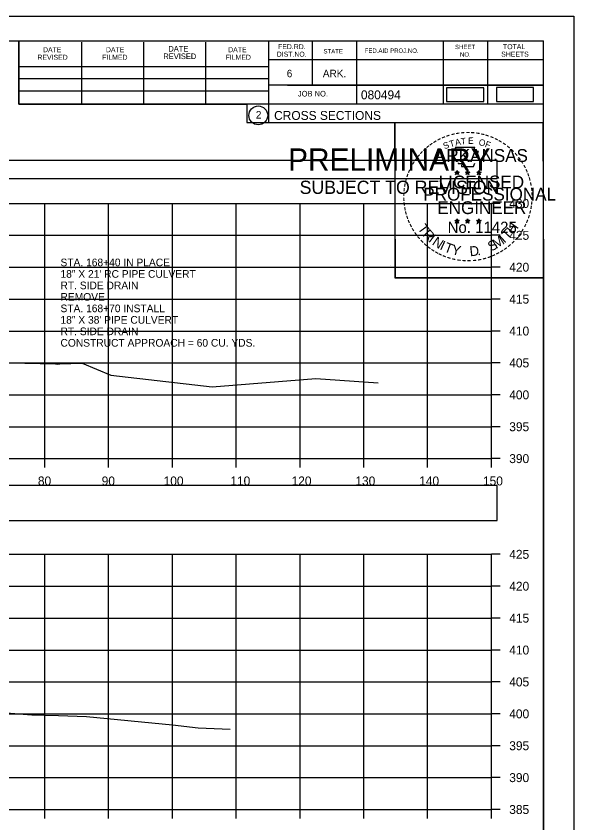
# Model space of a CAD drawing. Extents: x 1376273 to 1384221, y 378927 to 384592.
# Drawn here: x 1377933.8 to 1378021.2, y 381052.1 to 381178.5 of the extents above; entities that cross this region are included whole.
import ezdxf

# ---------------------------------------------------------------- set-up
doc = ezdxf.new("R2010")
doc.units = 0
for name, color, linetype in [('R_Axis', 7, 'Continuous'), ('R_Axis Annot', 7, 'Continuous'), ('R_Border', 7, 'Continuous'), ('R_Border PE', 7, 'Continuous'), ('R_Border Prem', 7, 'Continuous'), ('R_Drive', 7, 'Continuous'), ('R_Exist Surface', 7, 'Continuous'), ('R_Grid', 7, 'Continuous'), ('R_No Plot', 7, 'Continuous')]:
    doc.layers.add(name, color=color, linetype=linetype)

msp = doc.modelspace()

# ---------------------------------------------------------------- linework, layer by layer
at = {"layer": 'R_Axis'}
for p, q in [((1378008.28, 381109.17), (1378008.28, 381149.17)), ((1378009.68, 381149.17), (1378008.28, 381149.17)), ((1378009.68, 381144.17), (1378008.28, 381144.17)), ((1378009.68, 381139.17), (1378008.28, 381139.17)), ((1378009.68, 381134.17), (1378008.28, 381134.17)), ((1378009.68, 381129.17), (1378008.28, 381129.17)), ((1378009.68, 381124.17), (1378008.28, 381124.17)), ((1378009.68, 381119.17), (1378008.28, 381119.17)), ((1378009.68, 381114.17), (1378008.28, 381114.17)), ((1377708.28, 381109.17), (1378008.28, 381109.17)), ((1377938.28, 381107.77), (1377938.28, 381109.17)), ((1377948.28, 381107.77), (1377948.28, 381109.17)), ((1377958.28, 381107.77), (1377958.28, 381109.17)), ((1377968.28, 381107.77), (1377968.28, 381109.17)), ((1377978.28, 381107.77), (1377978.28, 381109.17)), ((1377988.28, 381107.77), (1377988.28, 381109.17)), ((1377998.28, 381107.77), (1377998.28, 381109.17)), ((1378008.28, 381107.77), (1378008.28, 381109.17)), ((1378009.68, 381109.17), (1378008.28, 381109.17)), ((1378008.28, 381054.17), (1378008.28, 381094.17)), ((1378009.68, 381094.17), (1378008.28, 381094.17)), ((1378009.68, 381089.17), (1378008.28, 381089.17)), ((1378009.68, 381084.17), (1378008.28, 381084.17)), ((1378009.68, 381079.17), (1378008.28, 381079.17)), ((1378009.68, 381074.17), (1378008.28, 381074.17)), ((1378009.68, 381069.17), (1378008.28, 381069.17)), ((1378009.68, 381064.17), (1378008.28, 381064.17)), ((1378009.68, 381059.17), (1378008.28, 381059.17)), ((1377708.28, 381054.17), (1378008.28, 381054.17)), ((1377938.28, 381052.77), (1377938.28, 381054.17)), ((1377948.28, 381052.77), (1377948.28, 381054.17)), ((1377958.28, 381052.77), (1377958.28, 381054.17)), ((1377968.28, 381052.77), (1377968.28, 381054.17)), ((1377978.28, 381052.77), (1377978.28, 381054.17)), ((1377988.28, 381052.77), (1377988.28, 381054.17)), ((1377998.28, 381052.77), (1377998.28, 381054.17)), ((1378008.28, 381052.77), (1378008.28, 381054.17)), ((1378009.68, 381054.17), (1378008.28, 381054.17))]:
    msp.add_line(p, q, dxfattribs=at)
at = {"layer": 'R_Axis Annot'}
for points in [[(1377707.37, 381153.1), (1378009.17, 381153.1), (1378009.17, 381155.92), (1377707.37, 381155.92)], [(1377707.37, 381099.45), (1378009.17, 381099.45), (1378009.17, 381104.97), (1377707.37, 381104.97)]]:
    msp.add_lwpolyline(points, close=True, dxfattribs=at)
at = {"layer": 'R_Border'}
for p, q in [((1377700.28, 381174.63), (1378016.46, 381174.63)), ((1377934.2, 381164.75), (1377934.2, 381174.63)), ((1377944.06, 381164.75), (1377944.06, 381174.43)), ((1377953.82, 381164.75), (1377953.82, 381174.43)), ((1377963.5, 381164.75), (1377963.5, 381174.43)), ((1377973.36, 381174.63), (1377973.36, 381161.83)), ((1377980.2, 381174.63), (1377980.2, 381167.69)), ((1377987.14, 381174.63), (1377987.14, 381164.75)), ((1378000.72, 381174.63), (1378000.72, 381164.75)), ((1378007.66, 381174.63), (1378007.66, 381164.75)), ((1378016.46, 380969.17), (1378016.46, 381174.63)), ((1378016.46, 381171.69), (1377973.36, 381171.69)), ((1378016.46, 381171.71), (1378016.46, 381171.71)), ((1377934.2, 381170.61), (1377973.36, 381170.61)), ((1377934.2, 381168.75), (1377973.36, 381168.75)), ((1378016.46, 381167.69), (1377973.36, 381167.69)), ((1377976.32, 381167.69), (1378016.46, 381167.69)), ((1377934.2, 381164.75), (1377934.2, 381166.81)), ((1377934.2, 381166.81), (1377973.36, 381166.81)), ((1378016.46, 381164.75), (1377934.2, 381164.75)), ((1377973.36, 381161.83), (1378016.46, 381161.83))]:
    msp.add_line(p, q, dxfattribs=at)
msp.add_circle((1377971.74, 381162.97), 1.47, dxfattribs=at)
at = {"layer": 'R_Border PE'}
for p, q in [((1378002.54, 381154.09), (1378002.89, 381153.97)), ((1378002.54, 381154.09), (1378002.8, 381154.04)), ((1378002.54, 381154.09), (1378002.78, 381153.96)), ((1378002.68, 381153.68), (1378002.89, 381153.97)), ((1378002.68, 381153.68), (1378002.8, 381153.92)), ((1378002.68, 381153.68), (1378002.89, 381153.89)), ((1378002.89, 381154.34), (1378002.85, 381154.09)), ((1378002.89, 381153.97), (1378002.89, 381154.34)), ((1378002.89, 381154.34), (1378002.94, 381154.09)), ((1378003.24, 381154.09), (1378002.89, 381153.97)), ((1378003.1, 381153.68), (1378002.89, 381153.97)), ((1378003.1, 381153.68), (1378002.89, 381153.89)), ((1378003.24, 381154.09), (1378002.95, 381154.04)), ((1378003.1, 381153.68), (1378002.97, 381153.97)), ((1378003.24, 381154.09), (1378003.03, 381153.98)), ((1378004.21, 381154.09), (1378004.56, 381153.97)), ((1378004.21, 381154.09), (1378004.47, 381154.04)), ((1378004.21, 381154.09), (1378004.45, 381153.96)), ((1378004.35, 381153.68), (1378004.56, 381153.97)), ((1378004.35, 381153.68), (1378004.47, 381153.92)), ((1378004.35, 381153.68), (1378004.56, 381153.89)), ((1378004.56, 381154.34), (1378004.52, 381154.09)), ((1378004.56, 381153.97), (1378004.56, 381154.34)), ((1378004.56, 381154.34), (1378004.61, 381154.09)), ((1378004.91, 381154.09), (1378004.56, 381153.97)), ((1378004.77, 381153.68), (1378004.56, 381153.97)), ((1378004.77, 381153.68), (1378004.56, 381153.89)), ((1378004.91, 381154.09), (1378004.62, 381154.04)), ((1378004.77, 381153.68), (1378004.64, 381153.97)), ((1378004.91, 381154.09), (1378004.7, 381153.98)), ((1378005.98, 381154.07), (1378006.33, 381153.96)), ((1378005.98, 381154.07), (1378006.23, 381154.03)), ((1378005.98, 381154.07), (1378006.21, 381153.95)), ((1378006.11, 381153.67), (1378006.33, 381153.96)), ((1378006.11, 381153.67), (1378006.24, 381153.91)), ((1378006.11, 381153.67), (1378006.32, 381153.88)), ((1378006.33, 381154.33), (1378006.28, 381154.08)), ((1378006.54, 381153.67), (1378006.32, 381153.88)), ((1378006.33, 381153.96), (1378006.33, 381154.33)), ((1378006.33, 381154.33), (1378006.37, 381154.08)), ((1378006.67, 381154.07), (1378006.33, 381153.96)), ((1378006.54, 381153.67), (1378006.33, 381153.96)), ((1378006.67, 381154.07), (1378006.39, 381154.02)), ((1378006.54, 381153.67), (1378006.4, 381153.96)), ((1378006.67, 381154.07), (1378006.47, 381153.97)), ((1378002.54, 381146.51), (1378002.89, 381146.4)), ((1378002.54, 381146.51), (1378002.79, 381146.47)), ((1378002.54, 381146.51), (1378002.78, 381146.39)), ((1378002.67, 381146.1), (1378002.89, 381146.4)), ((1378002.67, 381146.1), (1378002.8, 381146.35)), ((1378002.67, 381146.1), (1378002.89, 381146.32)), ((1378002.89, 381146.77), (1378002.85, 381146.51)), ((1378002.89, 381146.4), (1378002.89, 381146.77)), ((1378002.89, 381146.77), (1378002.94, 381146.52)), ((1378003.23, 381146.51), (1378002.89, 381146.4)), ((1378003.1, 381146.1), (1378002.89, 381146.4)), ((1378003.1, 381146.1), (1378002.89, 381146.32)), ((1378003.23, 381146.51), (1378002.95, 381146.46)), ((1378003.1, 381146.1), (1378002.96, 381146.4)), ((1378003.23, 381146.51), (1378003.03, 381146.41)), ((1378004.21, 381146.51), (1378004.56, 381146.4)), ((1378004.21, 381146.51), (1378004.46, 381146.47)), ((1378004.21, 381146.51), (1378004.44, 381146.39)), ((1378004.34, 381146.1), (1378004.56, 381146.4)), ((1378004.34, 381146.1), (1378004.47, 381146.35)), ((1378004.34, 381146.1), (1378004.55, 381146.32)), ((1378004.56, 381146.77), (1378004.52, 381146.51)), ((1378004.77, 381146.1), (1378004.55, 381146.32)), ((1378004.56, 381146.4), (1378004.56, 381146.77)), ((1378004.56, 381146.77), (1378004.61, 381146.52)), ((1378004.9, 381146.51), (1378004.56, 381146.4)), ((1378004.77, 381146.1), (1378004.56, 381146.4)), ((1378004.9, 381146.51), (1378004.62, 381146.46)), ((1378004.77, 381146.1), (1378004.63, 381146.4)), ((1378004.9, 381146.51), (1378004.7, 381146.41)), ((1378005.97, 381146.5), (1378006.32, 381146.39)), ((1378005.97, 381146.5), (1378006.23, 381146.46)), ((1378005.97, 381146.5), (1378006.21, 381146.38)), ((1378006.11, 381146.09), (1378006.32, 381146.39)), ((1378006.11, 381146.09), (1378006.23, 381146.34)), ((1378006.11, 381146.09), (1378006.32, 381146.31)), ((1378006.32, 381146.76), (1378006.28, 381146.5)), ((1378006.32, 381146.39), (1378006.32, 381146.76)), ((1378006.32, 381146.76), (1378006.37, 381146.51)), ((1378006.67, 381146.5), (1378006.32, 381146.39)), ((1378006.54, 381146.09), (1378006.32, 381146.39)), ((1378006.54, 381146.09), (1378006.32, 381146.31)), ((1378006.67, 381146.5), (1378006.38, 381146.45)), ((1378006.54, 381146.09), (1378006.4, 381146.39)), ((1378006.67, 381146.5), (1378006.47, 381146.4))]:
    msp.add_line(p, q, dxfattribs=at)
for points in [[(1378002.58, 381157.96), (1378002.85, 381157.14)], [(1378006.09, 381157.04), (1378006.24, 381157.33), (1378005.55, 381157.3), (1378005.7, 381157.96), (1378002.58, 381157.96)], [(1378003.08, 381155.54), (1378003.08, 381155.45), (1378003.64, 381155.43), (1378003.58, 381154.96), (1378005.45, 381154.96), (1378005.66, 381155.5)], [(1378002.89, 381154.34), (1378003.1, 381153.68), (1378002.54, 381154.09), (1378003.24, 381154.09), (1378002.68, 381153.68), (1378002.89, 381154.34)], [(1378004.56, 381154.34), (1378004.77, 381153.68), (1378004.21, 381154.09), (1378004.91, 381154.09), (1378004.35, 381153.68), (1378004.56, 381154.34)], [(1378006.33, 381154.33), (1378006.54, 381153.67), (1378005.98, 381154.07), (1378006.67, 381154.07), (1378006.11, 381153.67), (1378006.33, 381154.33)], [(1378002.89, 381146.77), (1378003.1, 381146.1), (1378002.54, 381146.51), (1378003.23, 381146.51), (1378002.67, 381146.1), (1378002.89, 381146.77)], [(1378004.56, 381146.77), (1378004.77, 381146.1), (1378004.21, 381146.51), (1378004.9, 381146.51), (1378004.34, 381146.1), (1378004.56, 381146.77)], [(1378006.32, 381146.76), (1378006.54, 381146.09), (1378005.97, 381146.5), (1378006.67, 381146.5), (1378006.11, 381146.09), (1378006.32, 381146.76)]]:
    msp.add_lwpolyline(points, dxfattribs=at)
for centre, radius in [((1378002.89, 381153.97), 0.172), ((1378002.89, 381153.97), 0.145), ((1378002.89, 381153.97), 0.116), ((1378002.89, 381153.97), 0.0991), ((1378002.89, 381153.97), 0.0747), ((1378002.89, 381153.97), 0.0495), ((1378002.89, 381153.97), 0.0296), ((1378004.56, 381153.97), 0.172), ((1378004.56, 381153.97), 0.145), ((1378004.56, 381153.97), 0.116), ((1378004.56, 381153.97), 0.0991), ((1378004.56, 381153.97), 0.0747), ((1378004.56, 381153.97), 0.0495), ((1378004.56, 381153.97), 0.0296), ((1378006.32, 381153.96), 0.172), ((1378006.32, 381153.96), 0.145), ((1378006.32, 381153.96), 0.116), ((1378006.32, 381153.96), 0.0991), ((1378006.32, 381153.96), 0.0747), ((1378006.32, 381153.96), 0.0495), ((1378006.32, 381153.96), 0.0296), ((1378002.89, 381146.4), 0.172), ((1378002.89, 381146.4), 0.145), ((1378002.89, 381146.4), 0.116), ((1378002.89, 381146.4), 0.0991), ((1378002.89, 381146.4), 0.0747), ((1378002.89, 381146.4), 0.0495), ((1378002.89, 381146.4), 0.0296), ((1378004.56, 381146.4), 0.172), ((1378004.56, 381146.4), 0.145), ((1378004.56, 381146.4), 0.116), ((1378004.56, 381146.4), 0.0991), ((1378004.56, 381146.4), 0.0747), ((1378004.56, 381146.4), 0.0495), ((1378004.56, 381146.4), 0.0296), ((1378006.32, 381146.39), 0.172), ((1378006.32, 381146.39), 0.145), ((1378006.32, 381146.39), 0.116), ((1378006.32, 381146.39), 0.0991), ((1378006.32, 381146.39), 0.0747), ((1378006.32, 381146.39), 0.0495), ((1378006.32, 381146.39), 0.0296)]:
    msp.add_circle(centre, radius, dxfattribs=at)
at = {"layer": 'R_Drive'}
for points in [[(1378001.25, 381165.13), (1378007.09, 381165.13), (1378007.09, 381167.31), (1378001.25, 381167.31)], [(1378009.06, 381165.13), (1378014.9, 381165.13), (1378014.9, 381167.32), (1378009.06, 381167.32)]]:
    msp.add_lwpolyline(points, close=True, dxfattribs=at)
at = {"layer": 'R_Exist Surface'}
for points in [[(1377927.43, 381124.32), (1377935.15, 381124.13), (1377939.95, 381124.01), (1377940.26, 381123.99), (1377940.61, 381124.01), (1377944.11, 381124.11), (1377948.65, 381122.25), (1377964.53, 381120.42), (1377980.75, 381121.74), (1377990.55, 381121.05)], [(1377927.44, 381069.67), (1377936.25, 381069.02), (1377940.44, 381068.92), (1377944.8, 381068.75), (1377958.29, 381067.44), (1377962.34, 381066.98), (1377967.32, 381066.77)]]:
    msp.add_lwpolyline(points, dxfattribs=at)
at = {"layer": 'R_Grid'}
for p, q in [((1377708.28, 381149.17), (1378008.28, 381149.17)), ((1377938.28, 381109.17), (1377938.28, 381149.17)), ((1377948.28, 381109.17), (1377948.28, 381149.17)), ((1377958.28, 381109.17), (1377958.28, 381149.17)), ((1377968.28, 381109.17), (1377968.28, 381149.17)), ((1377978.28, 381109.17), (1377978.28, 381149.17)), ((1377988.28, 381109.17), (1377988.28, 381149.17)), ((1377998.28, 381109.17), (1377998.28, 381149.17)), ((1378008.28, 381109.17), (1378008.28, 381149.17)), ((1377708.28, 381144.17), (1378008.28, 381144.17)), ((1377708.28, 381139.17), (1378008.28, 381139.17)), ((1377708.28, 381134.17), (1378008.28, 381134.17)), ((1377708.28, 381129.17), (1378008.28, 381129.17)), ((1377708.28, 381124.17), (1378008.28, 381124.17)), ((1377708.28, 381119.17), (1378008.28, 381119.17)), ((1377708.28, 381114.17), (1378008.28, 381114.17)), ((1377708.28, 381109.17), (1378008.28, 381109.17)), ((1377708.28, 381094.17), (1378008.28, 381094.17)), ((1377938.28, 381054.17), (1377938.28, 381094.17)), ((1377948.28, 381054.17), (1377948.28, 381094.17)), ((1377958.28, 381054.17), (1377958.28, 381094.17)), ((1377968.28, 381054.17), (1377968.28, 381094.17)), ((1377978.28, 381054.17), (1377978.28, 381094.17)), ((1377988.28, 381054.17), (1377988.28, 381094.17)), ((1377998.28, 381054.17), (1377998.28, 381094.17)), ((1378008.28, 381054.17), (1378008.28, 381094.17)), ((1377708.28, 381089.17), (1378008.28, 381089.17)), ((1377708.28, 381084.17), (1378008.28, 381084.17)), ((1377708.28, 381079.17), (1378008.28, 381079.17)), ((1377708.28, 381074.17), (1378008.28, 381074.17)), ((1377708.28, 381069.17), (1378008.28, 381069.17)), ((1377708.28, 381064.17), (1378008.28, 381064.17)), ((1377708.28, 381059.17), (1378008.28, 381059.17)), ((1377708.28, 381054.17), (1378008.28, 381054.17))]:
    msp.add_line(p, q, dxfattribs=at)
at = {"layer": 'R_No Plot'}
for p, q in [((1377687.88, 381178.52), (1378021.21, 381178.52)), ((1377992.49, 381139.37), (1377992.49, 381139.37))]:
    msp.add_line(p, q, dxfattribs=at)
for points in [[(1377687.87, 381178.52), (1378021.21, 381178.52), (1378021.21, 380965.19), (1377687.87, 380965.19)], [(1377934.2, 381174.63), (1377934.2, 381164.75), (1377969.93, 381164.75), (1377969.93, 381161.83), (1377993.13, 381161.83), (1377993.13, 381137.5), (1378016.46, 381137.5), (1378016.46, 380969.17), (1377700.28, 380969.17), (1377700.28, 381174.63)], [(1377993.13, 381161.83), (1378016.34, 381161.83), (1378016.46, 381137.5), (1377993.25, 381137.5)]]:
    msp.add_lwpolyline(points, close=True, dxfattribs=at)

# ---------------------------------------------------------------- texts
at = {"layer": 'R_Axis Annot'}
for s, height, p in [('430', 1.4, (1378011.08, 381148.47)), ('425', 1.4, (1378011.08, 381143.47)), ('STA. 168+40 IN PLACE', 1.2, (1377940.73, 381139.32)), ('420', 1.4, (1378011.08, 381138.47)), ('18" X 21\' RC PIPE CULVERT', 1.2, (1377940.73, 381137.52)), ('RT. SIDE DRAIN', 1.2, (1377940.73, 381135.72)), ('REMOVE ', 1.2, (1377940.73, 381133.92)), ('415', 1.4, (1378011.08, 381133.47)), ('STA. 168+70 INSTALL', 1.2, (1377940.73, 381132.12)), ('18" X 38\' PIPE CULVERT', 1.2, (1377940.73, 381130.32)), ('RT. SIDE DRAIN', 1.2, (1377940.73, 381128.52)), ('410', 1.4, (1378011.08, 381128.47)), ('CONSTRUCT APPROACH = 60 CU. YDS.', 1.2, (1377940.73, 381126.72)), ('405', 1.4, (1378011.08, 381123.47)), ('400', 1.4, (1378011.08, 381118.47)), ('395', 1.4, (1378011.08, 381113.47)), ('390', 1.4, (1378011.08, 381108.47)), ('80', 1.4, (1377937.19, 381104.97)), ('90', 1.4, (1377947.19, 381104.97)), ('100', 1.4, (1377956.9, 381104.97)), ('110', 1.4, (1377967.36, 381104.97)), ('120', 1.4, (1377976.96, 381104.97)), ('130', 1.4, (1377986.96, 381104.97)), ('140', 1.4, (1377996.96, 381104.97)), ('150', 1.4, (1378006.96, 381104.97)), ('425', 1.4, (1378011.08, 381093.47)), ('420', 1.4, (1378011.08, 381088.47)), ('415', 1.4, (1378011.08, 381083.47)), ('410', 1.4, (1378011.08, 381078.47)), ('405', 1.4, (1378011.08, 381073.47)), ('400', 1.4, (1378011.08, 381068.47)), ('395', 1.4, (1378011.08, 381063.47)), ('390', 1.4, (1378011.08, 381058.47)), ('385', 1.4, (1378011.08, 381053.47))]:
    msp.add_text(s, height=height, dxfattribs=at).set_placement(p)
at = {"layer": 'R_Border'}
for s, height, p in [('DATE', 0.879, (1377957.64, 381172.97)), ('FED.RD.', 0.782, (1377974.84, 381173.35)), ('SHEET', 0.684, (1378002.58, 381173.35)), ('TOTAL', 0.782, (1378010.1, 381173.35)), ('REVISED', 0.782, (1377937.12, 381171.69)), ('DATE', 0.782, (1377938, 381172.87)), ('FILMED', 0.782, (1377947.28, 381171.69)), ('DATE', 0.782, (1377947.86, 381172.87)), ('REVISED', 0.879, (1377956.86, 381171.79)), ('FILMED', 0.782, (1377966.62, 381171.69)), ('DATE', 0.782, (1377967.02, 381172.87)), ('DIST.NO.', 0.782, (1377974.64, 381172.17)), ('STATE', 0.684, (1377981.96, 381172.67)), ('FED.AID PROJ.NO.', 0.684, (1377988.42, 381172.77)), ('NO.', 0.684, (1378003.36, 381172.17)), ('SHEETS', 0.782, (1378009.82, 381172.17)), ('6', 1.17, (1377976.2, 381168.95)), ('ARK.', 1.172, (1377981.86, 381168.95)), ('JOB NO.', 0.879, (1377977.96, 381165.93)), ('080494', 1.4, (1377987.83, 381165.49)), ('2', 1.17, (1377971.36, 381162.48)), ('CROSS SECTIONS', 1.4, (1377974.22, 381162.26))]:
    msp.add_text(s, height=height, rotation=360, dxfattribs=at).set_placement(p)
at = {"layer": 'R_Border PE'}
for s, height, rotation, p in [('-', 1.6, 19.1761, (1378001.33, 381159.09)), ('-', 1.6, 13.6301, (1378002.08, 381159.33)), ('-', 1.6, 10.2193, (1378002.76, 381159.49)), ('-', 1.6, 5.8968, (1378003.49, 381159.6)), ('-', 1.6, 0.1862, (1378004.26, 381159.68)), ('-', 1.6, 357.743, (1378004.98, 381159.66)), ('-', 1.6, 352.1617, (1378005.73, 381159.61)), ('-', 1.6, 347.2049, (1378006.45, 381159.49)), ('-', 1.6, 342.3362, (1378007.08, 381159.34)), ('-', 1.6, 36.2317, (1377998.89, 381157.74)), ('-', 1.6, 34.0636, (1377999.47, 381158.13)), ('-', 1.6, 28.7918, (1378000.06, 381158.5)), ('-', 1.6, 24.3072, (1378000.7, 381158.82)), ('S', 1, 21.594, (1378000.94, 381157.64)), ('T', 1, 16.4036, (1378001.85, 381157.97)), ('A', 1, 11.2132, (1378002.68, 381158.22)), ('T', 1, 6.0228, (1378003.53, 381158.39)), ('E', 1, 0.8323, (1378004.63, 381158.5)), ('O', 1, 350.4515, (1378006.24, 381158.29)), ('F', 1, 340.0707, (1378007.19, 381158.06)), ('-', 1.6, 337.8551, (1378007.82, 381159.11)), ('-', 1.6, 334.1211, (1378008.45, 381158.84)), ('-', 1.6, 329.6409, (1378009.03, 381158.56)), ('-', 1.6, 325.8627, (1378009.67, 381158.2)), ('-', 1.6, 48.423, (1377997.53, 381156.47)), ('-', 1.6, 42.9622, (1377997.98, 381156.94)), ('-', 1.6, 38.9507, (1377998.41, 381157.36)), ('ARKANSAS', 2, 360, (1377999.44, 381155.68)), ('-', 1.6, 320.5297, (1378010.28, 381157.77)), ('-', 1.6, 315.5786, (1378010.88, 381157.29)), ('-', 1.6, 54.2325, (1377996.72, 381155.41)), ('-', 1.6, 50.6142, (1377997.13, 381155.98)), ('-', 1.6, 309.8797, (1378011.45, 381156.74)), ('-', 1.6, 306.6522, (1378011.97, 381156.13)), ('-', 1.6, 62.8713, (1377996.08, 381154.27)), ('-', 1.6, 58.0706, (1377996.39, 381154.89)), ('-', 1.4, 303.6753, (1378012.46, 381155.57)), ('-', 1.6, 299.6684, (1378012.78, 381154.96)), ('-', 1.6, 72.3945, (1377995.6, 381153.03)), ('-', 1.6, 67.7743, (1377995.82, 381153.66)), ('LICENSED', 2, 360, (1378000.03, 381151.53)), ('DWB', 0.01, 360, (1378002.88, 381153.97)), ('DWB', 0.01, 360, (1378004.55, 381153.97)), ('DWB', 0.01, 360, (1378006.31, 381153.96)), ('-', 1.6, 294.6628, (1378013.1, 381154.35)), ('-', 1.6, 290.5728, (1378013.36, 381153.77)), ('-', 1.6, 81.2013, (1377995.27, 381151.6)), ('-', 1.6, 75.461, (1377995.4, 381152.32)), ('-', 1.6, 285.1233, (1378013.59, 381153.19)), ('-', 1.6, 280.5493, (1378013.79, 381152.45)), ('-', 1.6, 85.1863, (1377995.19, 381150.91)), ('PROFESSIONAL', 2, 360, (1377997.61, 381149.62)), ('-', 1.6, 276.5962, (1378013.95, 381151.68)), ('-', 1.6, 94.1959, (1377995.2, 381149.49)), ('-', 1.6, 89.0622, (1377995.17, 381150.21)), ('-', 1.6, 274.3301, (1378014.01, 381150.96)), ('-', 1.6, 269.9407, (1378014.05, 381150.33)), ('-', 1.6, 98.9479, (1377995.28, 381148.82)), ('-', 1.6, 101.7149, (1377995.41, 381148.09)), ('ENGINEER', 2, 360, (1377999.8, 381147.5)), ('-', 1.6, 260.9953, (1378013.96, 381149.01)), ('-', 1.6, 263.5172, (1378014.03, 381149.66)), ('-', 1.6, 105.4578, (1377995.57, 381147.49)), ('-', 1.6, 109.0874, (1377995.79, 381146.86)), ('-', 1.6, 252.8681, (1378013.67, 381147.61)), ('-', 1.6, 255.7626, (1378013.85, 381148.33)), ('-', 1.6, 114.0643, (1377996.04, 381146.27)), ('-', 1.6, 115.7289, (1377996.35, 381145.65)), ('T', 1.54, 306.0406, (1377996.65, 381145.24)), ('No. 11425', 1.757, 360, (1378001.42, 381144.55)), ('DWB', 0.01, 360, (1378002.87, 381146.4)), ('DWB', 0.01, 360, (1378004.54, 381146.4)), ('DWB', 0.01, 360, (1378006.31, 381146.39)), ('H', 1.54, 54.6088, (1378011.77, 381144.27)), ('-', 1.6, 244.6197, (1378013.18, 381146.31)), ('-', 1.6, 247.8887, (1378013.44, 381146.93)), ('-', 1.6, 120.4471, (1377996.7, 381145.06)), ('-', 1.6, 125.8934, (1377997.11, 381144.5)), ('R', 1.54, 314.005, (1377997.41, 381144.19)), ('T', 1.54, 46.6444, (1378010.88, 381143.33)), ('-', 1.6, 239.0712, (1378012.79, 381145.55)), ('-', 1.6, 130.7181, (1377997.57, 381143.95)), ('-', 1.6, 134.2238, (1377998.09, 381143.4)), ('I', 1.54, 321.9694, (1377998.31, 381143.26)), ('N', 1.54, 326.5002, (1377998.88, 381142.79)), ('S', 1.54, 26.9312, (1378008.19, 381141.6)), ('M', 1.54, 32.6563, (1378009.03, 381142.01)), ('I', 1.54, 42.1136, (1378010.32, 381142.85)), ('-', 1.6, 231.2538, (1378011.96, 381144.33)), ('-', 1.6, 233.8452, (1378012.39, 381144.9)), ('-', 1.6, 138.9338, (1377998.61, 381142.94)), ('-', 1.6, 144.6463, (1377999.17, 381142.53)), ('I', 1.54, 335.3603, (1378000.08, 381142)), ('T', 1.54, 339.8912, (1378000.75, 381141.67)), ('Y', 1.54, 347.8556, (1378001.96, 381141.23)), ('D', 1.54, 6.3969, (1378004.95, 381140.87)), ('-', 1.6, 215.7363, (1378010.41, 381142.79)), ('-', 1.6, 221.0851, (1378010.95, 381143.26)), ('-', 1.6, 225.7653, (1378011.48, 381143.77)), ('-', 1.6, 148.0898, (1377999.73, 381142.16)), ('-', 1.6, 151.5704, (1378000.31, 381141.84)), ('-', 1.6, 154.6002, (1378000.83, 381141.59)), ('-', 1.6, 158.5612, (1378001.45, 381141.34)), ('.', 1.54, 13.7642, (1378006.14, 381141)), ('-', 1.6, 200.7184, (1378008.07, 381141.46)), ('-', 1.6, 204.2516, (1378008.69, 381141.74)), ('-', 1.6, 207.3568, (1378009.31, 381142.06)), ('-', 1.6, 212.2491, (1378009.87, 381142.4)), ('-', 1.6, 162.7983, (1378002.14, 381141.12)), ('-', 1.6, 167.5555, (1378002.86, 381140.96)), ('-', 1.6, 173.1155, (1378003.63, 381140.85)), ('-', 1.6, 176.5183, (1378004.38, 381140.8)), ('-', 1.6, 181.5918, (1378005.12, 381140.82)), ('-', 1.6, 185.8167, (1378005.93, 381140.89)), ('-', 1.6, 191.2858, (1378006.66, 381141.02)), ('-', 1.6, 195.4743, (1378007.39, 381141.22))]:
    msp.add_text(s, height=height, rotation=rotation, dxfattribs=at).set_placement(p)
at = {"layer": 'R_Border Prem'}
for s, height, p in [('PRELIMINARY', 3.5, (1377976.41, 381154.29)), ('DWB', 0.01, (1377977.15, 381156.14)), ('SUBJECT TO REVISION', 2.0751, (1377978.22, 381150.66))]:
    msp.add_text(s, height=height, rotation=360, dxfattribs=at).set_placement(p)

doc.saveas('drawing.dxf')
